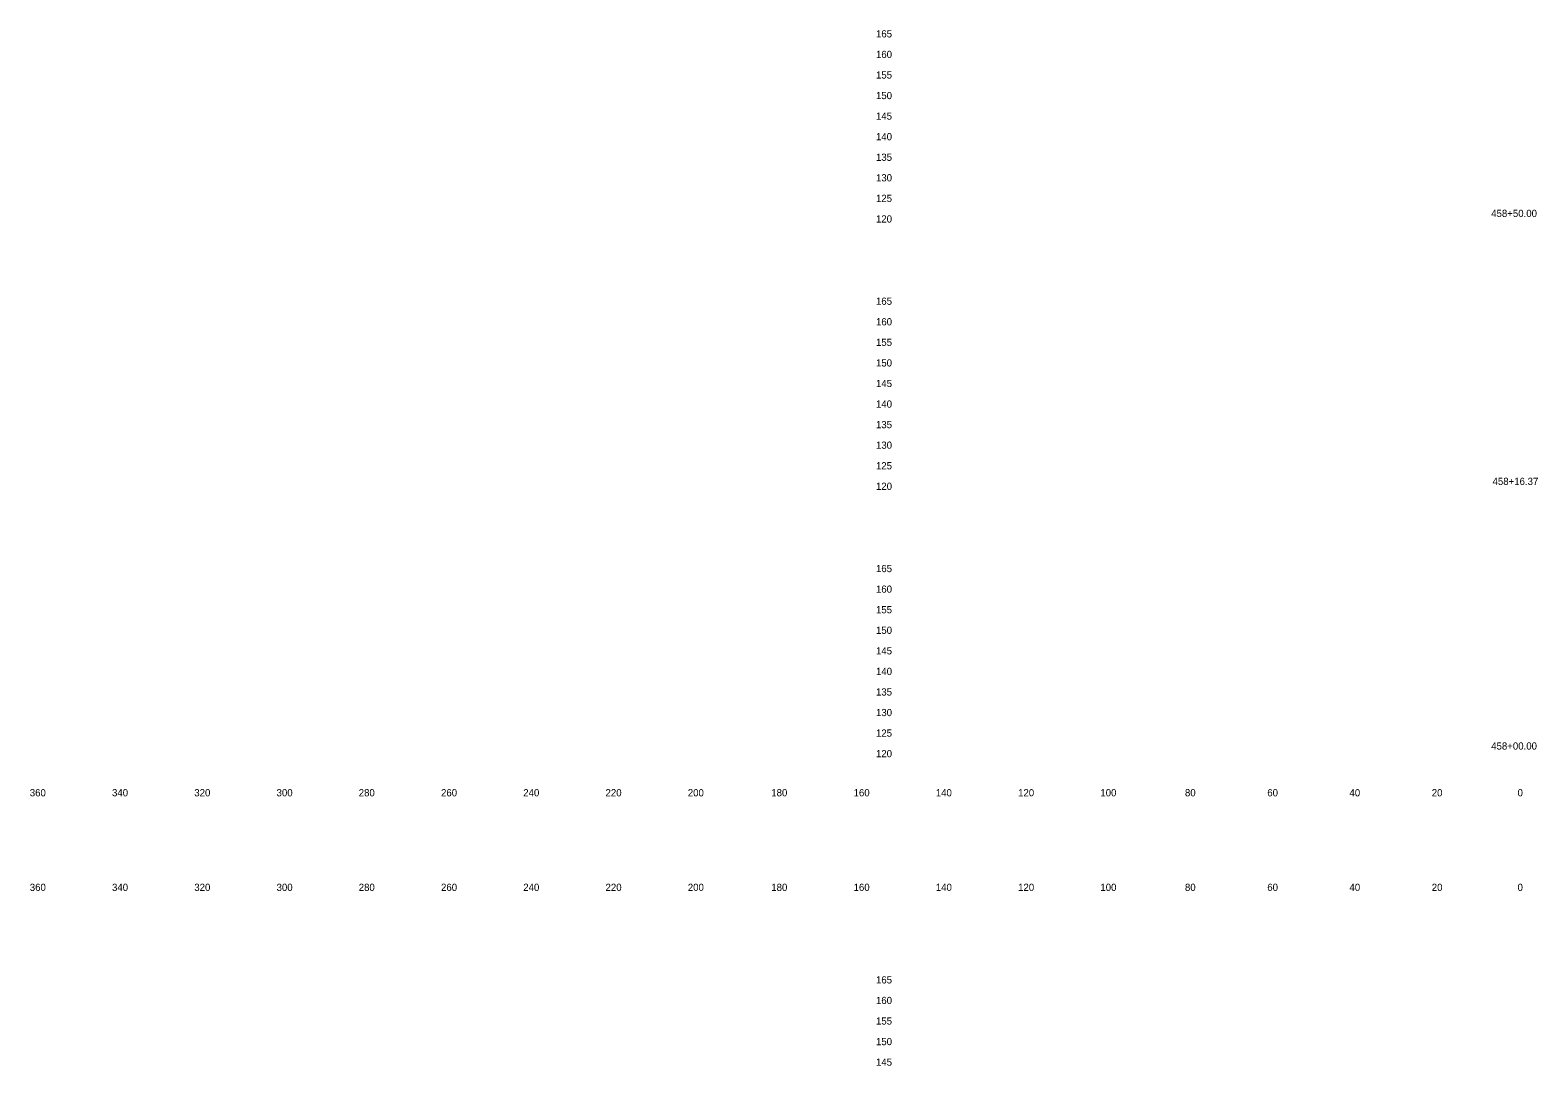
# Model space of a CAD drawing. Extents: x 21281 to 22024, y 6472 to 15198.
# Drawn here: x 21280.5 to 21647, y 7559.8 to 7811.6 of the extents above; entities that cross this region are included whole.
import ezdxf

# ---------------------------------------------------------------- set-up
doc = ezdxf.new("R2010")
doc.units = 0
for name, color, linetype in [('Draft_XS_Grid', 7, 'Continuous'), ('Draft_XS_Text', 7, 'Continuous'), ('SLOPE_STAKES_FILL', 7, 'Continuous')]:
    doc.layers.add(name, color=color, linetype=linetype)

msp = doc.modelspace()

# ---------------------------------------------------------------- texts
at = {"layer": 'Draft_XS_Grid'}
for s, p in [('  165  ', (21484.84, 7809.84)), ('  160  ', (21484.84, 7804.84)), ('  155  ', (21484.84, 7799.84)), ('  150  ', (21484.84, 7794.84)), ('  145  ', (21484.84, 7789.84)), ('  140  ', (21484.84, 7784.84)), ('  135  ', (21484.84, 7779.84)), ('  130  ', (21484.84, 7774.84)), ('  125  ', (21484.84, 7769.84)), ('  120  ', (21484.84, 7764.84)), ('  165  ', (21484.84, 7744.84)), ('  160  ', (21484.84, 7739.84)), ('  155  ', (21484.84, 7734.84)), ('  150  ', (21484.84, 7729.84)), ('  145  ', (21484.84, 7724.84)), ('  140  ', (21484.84, 7719.84)), ('  135  ', (21484.84, 7714.84)), ('  130  ', (21484.84, 7709.84)), ('  125  ', (21484.84, 7704.84)), ('  120  ', (21484.84, 7699.84)), ('  165  ', (21484.84, 7679.84)), ('  160  ', (21484.84, 7674.84)), ('  155  ', (21484.84, 7669.84)), ('  150  ', (21484.84, 7664.84)), ('  145  ', (21484.84, 7659.84)), ('  140  ', (21484.84, 7654.84)), ('  135  ', (21484.84, 7649.84)), ('  130  ', (21484.84, 7644.84)), ('  125  ', (21484.84, 7639.84)), ('  120  ', (21484.84, 7634.84)), ('  165  ', (21484.84, 7579.84)), ('  160  ', (21484.84, 7574.84)), ('  155  ', (21484.84, 7569.84)), ('  150  ', (21484.84, 7564.84)), ('  145  ', (21484.84, 7559.84))]:
    msp.add_text(s, height=1.75, dxfattribs=at).set_placement(p)
at = {"layer": 'Draft_XS_Text'}
for s, p in [('  360  ', (21279.14, 7625.34)), ('  340  ', (21299.13, 7625.34)), ('  320  ', (21319.13, 7625.34)), ('  300  ', (21339.13, 7625.34)), ('  280  ', (21359.1, 7625.34)), ('  260  ', (21379.11, 7625.34)), ('  240  ', (21399.1, 7625.34)), ('  220  ', (21419.1, 7625.34)), ('  200  ', (21439.1, 7625.34)), ('  180  ', (21459.39, 7625.34)), ('  160  ', (21479.4, 7625.34)), ('  140  ', (21499.39, 7625.34)), ('  120  ', (21519.39, 7625.34)), ('  100  ', (21539.39, 7625.34)), ('  80  ', (21559.95, 7625.34)), ('  60  ', (21579.97, 7625.34)), ('  40  ', (21599.95, 7625.34)), ('  20  ', (21619.95, 7625.34)), ('  0  ', (21640.81, 7625.34)), ('  0  ', (21640.81, 7625.34)), ('  360  ', (21279.14, 7602.34)), ('  340  ', (21299.13, 7602.34)), ('  320  ', (21319.13, 7602.34)), ('  300  ', (21339.13, 7602.34)), ('  280  ', (21359.1, 7602.34)), ('  260  ', (21379.11, 7602.34)), ('  240  ', (21399.1, 7602.34)), ('  220  ', (21419.1, 7602.34)), ('  200  ', (21439.1, 7602.34)), ('  180  ', (21459.39, 7602.34)), ('  160  ', (21479.4, 7602.34)), ('  140  ', (21499.39, 7602.34)), ('  120  ', (21519.39, 7602.34)), ('  100  ', (21539.39, 7602.34)), ('  80  ', (21559.95, 7602.34)), ('  60  ', (21579.97, 7602.34)), ('  40  ', (21599.95, 7602.34)), ('  20  ', (21619.95, 7602.34)), ('  0  ', (21640.81, 7602.34)), ('  0  ', (21640.81, 7602.34))]:
    msp.add_text(s, height=1.75, dxfattribs=at).set_placement(p)
at = {"layer": 'SLOPE_STAKES_FILL'}
for s, p in [('  458+50.00  ', (21634.4, 7766.19)), ('  458+16.37  ', (21634.73, 7701.04)), ('  458+00.00  ', (21634.4, 7636.7))]:
    msp.add_text(s, height=1.75, dxfattribs=at).set_placement(p)

doc.saveas('drawing.dxf')
